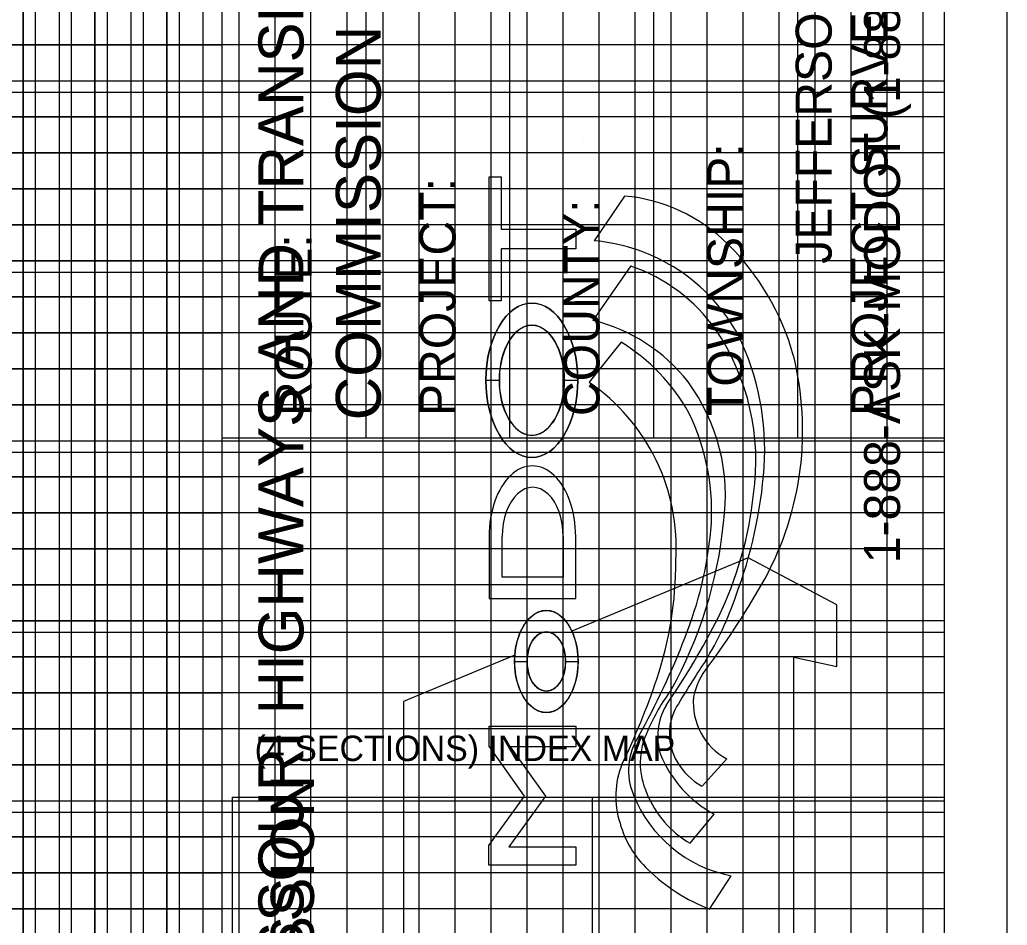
# Model space of a CAD drawing. Extents: x -0.2 to 31.7, y -0.2 to 20.6.
# Drawn here: x 28.681 to 31.425, y 5.654 to 8.169 of the extents above; entities that cross this region are included whole.
import ezdxf

# ---------------------------------------------------------------- set-up
doc = ezdxf.new("R2010")
doc.units = 0
for name, color, linetype in [('Border-Border', 7, 'Continuous'), ('Border-Bridge survey map and note', 7, 'Continuous'), ('Border-Cookie Cutter Template', 7, 'Continuous'), ('Border-English bridge partial major lines', 7, 'Continuous'), ('Border-English bridge partial minor lines', 7, 'Continuous'), ('Border-English bridge xsection major lines', 7, 'Continuous'), ('Border-English bridge xsection minor lines', 7, 'Continuous'), ('Border-English xsection major lines', 7, 'Continuous'), ('Border-English xsection minor lines', 7, 'Continuous'), ('Border-Full profile major grid lines', 7, 'Continuous'), ('Border-Geopak xsection major grid lines', 7, 'Continuous'), ('Border-Geopak xsection minor lines 1', 7, 'Continuous'), ('Border-Geopak xsection minor lines 2', 7, 'Continuous'), ('Border-Plan-profile major grid lines', 7, 'Continuous'), ('Border-Plotting block', 7, 'Continuous'), ('Border-Title block - A-size Landscape Electronic Seal', 7, 'Continuous'), ('Border-Title block - Final Plans Consultant Manual Seal', 7, 'Continuous'), ('Border-Title block - Final Plans Electronic Seal', 7, 'Continuous'), ('Border-Title block - Location Survey Electronic Seal', 7, 'Continuous'), ('Border-Xsection shape', 7, 'Continuous')]:
    doc.layers.add(name, color=color, linetype=linetype)

msp = doc.modelspace()

# ---------------------------------------------------------------- linework, layer by layer
at = {"layer": 'Border-Border'}
msp.add_line((31.25, 20.375), (31.25, 0), dxfattribs=at)
at = {"layer": 'Border-Bridge survey map and note'}
msp.add_line((30.2719, 6.0094), (30.2719, 3.9921), dxfattribs=at)
msp.add_lwpolyline([(29.2719, 3.9921), (29.2719, 6.0094), (31.2499, 6.0094)], dxfattribs=at)
at = {"layer": 'Border-Cookie Cutter Template'}
for p, q in [((29.2421, 20.375), (29.2421, 0)), ((31.2499, 20.375), (31.2499, 0))]:
    msp.add_line(p, q, dxfattribs=at)
at = {"layer": 'Border-English bridge partial major lines'}
for p, q in [((29.4899, 4), (29.4899, 20.375)), ((30.4899, 20.375), (30.4899, 4)), ((0, 8), (31.2499, 8)), ((0, 7), (31.2499, 7)), ((0, 6), (31.2499, 6))]:
    msp.add_line(p, q, dxfattribs=at)
at = {"layer": 'Border-English bridge partial minor lines'}
for p, q in [((28.6899, 20.375), (28.6899, 4)), ((28.7899, 20.375), (28.7899, 4)), ((28.8899, 20.375), (28.8899, 4)), ((28.9899, 20.375), (28.9899, 4)), ((29.0899, 20.375), (29.0899, 4)), ((29.1899, 20.375), (29.1899, 4)), ((29.2899, 20.375), (29.2899, 4)), ((29.3899, 20.375), (29.3899, 4)), ((29.5899, 20.375), (29.5899, 4)), ((29.6899, 20.375), (29.6899, 4)), ((29.7899, 20.375), (29.7899, 4)), ((29.8899, 20.375), (29.8899, 4)), ((29.9899, 20.375), (29.9899, 4)), ((30.0899, 20.375), (30.0899, 4)), ((30.1899, 20.375), (30.1899, 4)), ((30.2899, 20.375), (30.2899, 4)), ((30.3899, 20.375), (30.3899, 4)), ((30.5899, 20.375), (30.5899, 4)), ((30.6899, 20.375), (30.6899, 4)), ((30.7899, 20.375), (30.7899, 4)), ((30.8899, 20.375), (30.8899, 4)), ((30.9899, 20.375), (30.9899, 4)), ((31.0899, 20.375), (31.0899, 4)), ((31.1899, 20.375), (31.1899, 4)), ((31.2499, 8.1), (0, 8.1)), ((31.2499, 7.9), (0, 7.9)), ((31.2499, 7.8), (0, 7.8)), ((31.2499, 7.7), (0, 7.7)), ((31.2499, 7.6), (0, 7.6)), ((31.2499, 7.5), (0, 7.5)), ((31.2499, 7.4), (0, 7.4)), ((31.2499, 7.3), (0, 7.3)), ((31.2499, 7.2), (0, 7.2)), ((31.2499, 7.1), (0, 7.1)), ((31.2499, 6.9), (0, 6.9)), ((31.2499, 6.8), (0, 6.8)), ((31.2499, 6.7), (0, 6.7)), ((31.2499, 6.6), (0, 6.6)), ((31.2499, 6.5), (0, 6.5)), ((31.2499, 6.4), (0, 6.4)), ((31.2499, 6.3), (0, 6.3)), ((31.2499, 6.2), (0, 6.2)), ((31.2499, 6.1), (0, 6.1)), ((31.2499, 5.9), (0, 5.9)), ((31.2499, 5.8), (0, 5.8)), ((31.2499, 5.7), (0, 5.7))]:
    msp.add_line(p, q, dxfattribs=at)
at = {"layer": 'Border-English bridge xsection major lines'}
for p, q in [((29.4899, 3.9921), (29.4899, 20.375)), ((30.4899, 20.375), (30.4899, 3.9921)), ((0, 8), (31.2499, 8)), ((0, 7), (31.2499, 7)), ((0, 6), (31.2499, 6))]:
    msp.add_line(p, q, dxfattribs=at)
at = {"layer": 'Border-English bridge xsection minor lines'}
for p, q in [((28.6899, 20.375), (28.6899, 3.9921)), ((28.7899, 20.375), (28.7899, 3.9921)), ((28.8899, 20.375), (28.8899, 3.9921)), ((28.9899, 20.375), (28.9899, 3.9921)), ((29.0899, 20.375), (29.0899, 3.9921)), ((29.1899, 20.375), (29.1899, 3.9921)), ((29.2899, 20.375), (29.2899, 3.9921)), ((29.3899, 20.375), (29.3899, 3.9921)), ((29.5899, 20.375), (29.5899, 3.9921)), ((29.6899, 20.375), (29.6899, 3.9921)), ((29.7899, 20.375), (29.7899, 3.9921)), ((29.8899, 20.375), (29.8899, 3.9921)), ((29.9899, 20.375), (29.9899, 3.9921)), ((30.0899, 20.375), (30.0899, 3.9921)), ((30.1899, 20.375), (30.1899, 3.9921)), ((30.2899, 20.375), (30.2899, 3.9921)), ((30.3899, 20.375), (30.3899, 3.9921)), ((30.5899, 20.375), (30.5899, 3.9921)), ((30.6899, 20.375), (30.6899, 3.9921)), ((30.7899, 20.375), (30.7899, 3.9921)), ((30.8899, 20.375), (30.8899, 3.9921)), ((30.9899, 20.375), (30.9899, 3.9921)), ((31.0899, 20.375), (31.0899, 3.9921)), ((31.1899, 20.375), (31.1899, 3.9921)), ((31.2499, 8.1), (0, 8.1)), ((31.2499, 7.9), (0, 7.9)), ((31.2499, 7.8), (0, 7.8)), ((31.2499, 7.7), (0, 7.7)), ((31.2499, 7.6), (0, 7.6)), ((31.2499, 7.5), (0, 7.5)), ((31.2499, 7.4), (0, 7.4)), ((31.2499, 7.3), (0, 7.3)), ((31.2499, 7.2), (0, 7.2)), ((31.2499, 7.1), (0, 7.1)), ((31.2499, 6.9), (0, 6.9)), ((31.2499, 6.8), (0, 6.8)), ((31.2499, 6.7), (0, 6.7)), ((31.2499, 6.6), (0, 6.6)), ((31.2499, 6.5), (0, 6.5)), ((31.2499, 6.4), (0, 6.4)), ((31.2499, 6.3), (0, 6.3)), ((31.2499, 6.2), (0, 6.2)), ((31.2499, 6.1), (0, 6.1)), ((31.2499, 5.9), (0, 5.9)), ((31.2499, 5.8), (0, 5.8)), ((31.2499, 5.7), (0, 5.7))]:
    msp.add_line(p, q, dxfattribs=at)
at = {"layer": 'Border-English xsection major lines'}
for p, q in [((0, 8), (29.2421, 8)), ((0, 7), (29.2421, 7)), ((0, 6), (29.2421, 6))]:
    msp.add_line(p, q, dxfattribs=at)
at = {"layer": 'Border-English xsection minor lines'}
for p, q in [((28.6899, 0), (28.6899, 20.375)), ((28.8899, 0), (28.8899, 20.375)), ((29.0899, 0), (29.0899, 20.375)), ((0, 7.8), (29.2421, 7.8)), ((0, 7.6), (29.2421, 7.6)), ((0, 7.4), (29.2421, 7.4)), ((0, 7.2), (29.2421, 7.2)), ((0, 6.8), (29.2421, 6.8)), ((0, 6.6), (29.2421, 6.6)), ((0, 6.4), (29.2421, 6.4)), ((0, 6.2), (29.2421, 6.2)), ((0, 5.8), (29.2421, 5.8))]:
    msp.add_line(p, q, dxfattribs=at)
at = {"layer": 'Border-Full profile major grid lines'}
for p, q in [((29.2421, 7.5), (0, 7.5)), ((29.2421, 6.5), (0, 6.5))]:
    msp.add_line(p, q, dxfattribs=at)
at = {"layer": 'Border-Geopak xsection major grid lines'}
for p, q in [((0, 8), (29.2421, 8)), ((0, 7), (29.2421, 7)), ((0, 6), (29.2421, 6))]:
    msp.add_line(p, q, dxfattribs=at)
at = {"layer": 'Border-Geopak xsection minor lines 1'}
for p, q in [((28.7249, 0), (28.7249, 20.375)), ((28.9249, 0), (28.9249, 20.375)), ((29.1249, 0), (29.1249, 20.375)), ((0, 8.1), (29.2421, 8.1)), ((0, 7.9), (29.2421, 7.9)), ((0, 7.7), (29.2421, 7.7)), ((0, 7.5), (29.2421, 7.5)), ((0, 7.3), (29.2421, 7.3)), ((0, 7.1), (29.2421, 7.1)), ((0, 6.9), (29.2421, 6.9)), ((0, 6.7), (29.2421, 6.7)), ((0, 6.5), (29.2421, 6.5)), ((0, 6.3), (29.2421, 6.3)), ((0, 6.1), (29.2421, 6.1)), ((0, 5.9), (29.2421, 5.9)), ((0, 5.7), (29.2421, 5.7))]:
    msp.add_line(p, q, dxfattribs=at)
at = {"layer": 'Border-Geopak xsection minor lines 2'}
for p, q in [((28.8249, 0), (28.8249, 20.375)), ((29.0249, 0), (29.0249, 20.375)), ((0, 7.8), (29.2421, 7.8)), ((0, 7.6), (29.2421, 7.6)), ((0, 7.4), (29.2421, 7.4)), ((0, 7.2), (29.2421, 7.2)), ((0, 6.8), (29.2421, 6.8)), ((0, 6.6), (29.2421, 6.6)), ((0, 6.4), (29.2421, 6.4)), ((0, 6.2), (29.2421, 6.2)), ((0, 5.8), (29.2421, 5.8))]:
    msp.add_line(p, q, dxfattribs=at)
at = {"layer": 'Border-Plan-profile major grid lines'}
for p, q in [((29.2421, 7.5), (0, 7.5)), ((29.2421, 6.5), (0, 6.5))]:
    msp.add_line(p, q, dxfattribs=at)
at = {"layer": 'Border-Plotting block'}
msp.add_lwpolyline([(-0.175, -0.2125), (31.4249, -0.2125), (31.4249, 20.5875), (-0.175, 20.5875)], close=True, dxfattribs=at)
at = {"layer": 'Border-Title block - A-size Landscape Electronic Seal'}
for p, q in [((31.25, 7.9671), (25.6536, 7.9671)), ((29.1165, 7.7171), (29.1165, 7.7171)), ((31.2499, 7.4671), (25.6536, 7.4671)), ((29.1165, 7.2171), (29.1165, 7.2171)), ((31.25, 6.9671), (25.6536, 6.9671)), ((29.1165, 6.7171), (29.1165, 6.7171)), ((31.25, 6.4671), (25.6536, 6.4671)), ((29.1165, 6.2171), (29.1165, 6.2171)), ((31.25, 5.9671), (25.6536, 5.9671)), ((29.1165, 5.7171), (29.1165, 5.7171))]:
    msp.add_line(p, q, dxfattribs=at)
at = {"layer": 'Border-Title block - Final Plans Consultant Manual Seal'}
for p, q in [((29.2421, 20.375), (29.2421, 0)), ((30.3615, 7.6797), (30.2769, 7.5555)), ((30.3791, 7.4854), (30.2733, 7.3343)), ((30.3522, 7.2734), (30.2628, 7.1622)), ((29.985, 6.7339), (29.985, 6.5615)), ((30.0213, 6.6209), (30.0213, 6.7339)), ((30.1912, 6.7339), (30.1912, 6.6209)), ((30.2258, 6.5615), (30.2258, 6.7339)), ((30.7053, 6.6744), (30.2153, 6.4706)), ((30.9517, 6.5441), (30.7053, 6.6744)), ((30.1912, 6.6209), (30.0213, 6.6209)), ((29.985, 6.5615), (30.2258, 6.5615)), ((30.9517, 6.373), (30.9517, 6.5441)), ((30.0565, 6.4045), (29.747, 6.2758)), ((30.8321, 5.5668), (30.8321, 6.3984)), ((30.8321, 6.3984), (30.9517, 6.373)), ((29.747, 6.2758), (29.747, 5.3974)), ((30.5767, 6.04), (30.646, 6.116)), ((30.5438, 5.8818), (30.6107, 5.9623)), ((30.5979, 5.6989), (30.6579, 5.7914))]:
    msp.add_line(p, q, dxfattribs=at)
for points in [[(29.9849, 7.389), (29.9849, 7.7334), (30.0184, 7.7334), (30.0184, 7.588), (30.2258, 7.588), (30.2258, 7.5334), (30.0184, 7.5334), (30.0184, 7.389)], [(30.2258, 5.8212), (29.9842, 5.8212), (29.9842, 5.8757), (30.0838, 6.0126), (29.985, 6.1513), (29.985, 6.2068), (30.2258, 6.2068), (30.2258, 6.1494), (30.0435, 6.1494), (30.1414, 6.0126), (30.0397, 5.8719), (30.2258, 5.8719)]]:
    msp.add_lwpolyline(points, close=True, dxfattribs=at)
for centre, radius, start, end in [((30.3202, 7.216), 0.4656, 45.1693, 84.902), ((30.2326, 7.0506), 0.5069, 28.5725, 84.9889), ((30.1542, 7.0462), 0.7029, 15.8221, 45.3322), ((30.2197, 7.0262), 0.486, 35.4806, 70.8474), ((30.1611, 6.8707), 0.477, 37.8205, 76.3964), ((30.0712, 6.9433), 0.6553, 351.9272, 33.854), ((30.0697, 6.8139), 0.5393, 29.2666, 58.4191), ((30.0168, 6.9735), 0.7342, 356.2526, 25.8037), ((29.9956, 7.0284), 0.8608, 331.4589, 14.0852), ((29.9506, 6.7041), 0.5543, 55.7274, 55.7276), ((29.9506, 6.7041), 0.5543, 356.1033, 55.7272), ((30.1104, 6.8473), 0.5315, 351.8718, 36.464), ((29.9769, 6.803), 0.6267, 355.2048, 25.9837), ((29.4842, 7.0174), 1.2685, 339.2778, 355.8465), ((29.6781, 6.964), 1.048, 334.3097, 353.8237), ((29.4488, 6.8906), 1.1937, 330.8019, 354.3058), ((29.5189, 6.8555), 1.0875, 338.3366, 354.4662), ((29.4882, 6.6604), 1.0155, 341.469, 0.3416), ((28.8337, 7.6858), 2.1957, 323.2547, 330.8755), ((29.842, 6.8469), 0.8742, 328.3334, 341.428), ((28.754, 7.4559), 2.0944, 325.3377, 333.1413), ((28.5215, 7.2271), 2.1518, 330.8271, 338.9455), ((33.303, 4.5835), 3.2616, 146.4094, 149.0393), ((30.7373, 6.252), 0.1877, 140.188, 168.8506), ((28.4178, 7.0312), 2.1483, 334.3727, 341.1665), ((30.9575, 5.9676), 0.5778, 143.8762, 156.8714), ((30.7295, 6.2721), 0.177, 174.7527, 241.8661), ((30.6205, 6.1797), 0.167, 149.4043, 197.7638), ((30.6386, 6.1857), 0.1526, 150.2552, 210.6413), ((30.5453, 6.0841), 0.1729, 147.0199, 203.0239), ((30.6045, 6.1048), 0.1996, 153.2735, 205.15), ((30.7669, 6.2525), 0.3295, 202.0629, 241.7201), ((30.5743, 6.012), 0.2373, 157.7092, 198.1728), ((30.6772, 6.212), 0.1993, 211.4954, 239.6897), ((30.7282, 6.1528), 0.3681, 201.7288, 258.9961), ((30.6828, 6.1237), 0.279, 201.8104, 240.1114), ((30.6128, 6.0089), 0.2733, 195.0361, 226.9912), ((30.7761, 6.1649), 0.4989, 225.4988, 249.0787)]:
    msp.add_arc(centre, radius, start, end, dxfattribs=at)
for centre, major_axis, ratio in [((30.1038, 7.168), (0, 0.2144), 0.595517), ((30.1038, 7.1679), (0, -0.153), 0.589579), ((30.1441, 6.3867), (0, 0.1416), 0.623747), ((30.1441, 6.3867), (0, 0.0823), 0.65252)]:
    msp.add_ellipse(centre, major_axis=major_axis, ratio=ratio, dxfattribs=at)
for centre, major_axis, ratio in [((30.1053, 6.7338), (0, -0.1961), 0.614143), ((30.1062, 6.7338), (0, -0.1368), 0.62091)]:
    msp.add_ellipse(centre, major_axis=major_axis, ratio=ratio, start_param=1.570796, end_param=4.712389, dxfattribs=at)
at = {"layer": 'Border-Title block - Final Plans Electronic Seal'}
for p, q in [((29.2421, 20.375), (29.2421, 0)), ((30.3615, 7.6797), (30.2769, 7.5555)), ((30.3791, 7.4854), (30.2733, 7.3343)), ((30.3522, 7.2734), (30.2628, 7.1622)), ((29.9761, 7.1679), (30.0136, 7.1679)), ((29.9761, 7.1679), (30.0136, 7.1679)), ((30.194, 7.1679), (30.2315, 7.1679)), ((30.194, 7.1679), (30.2315, 7.1679)), ((29.985, 6.7339), (29.985, 6.5615)), ((30.0213, 6.6209), (30.0213, 6.7339)), ((30.1912, 6.7339), (30.1912, 6.6209)), ((30.2258, 6.5615), (30.2258, 6.7339)), ((30.7053, 6.6744), (30.2153, 6.4706)), ((30.9517, 6.5441), (30.7053, 6.6744)), ((30.1912, 6.6209), (30.0213, 6.6209)), ((29.985, 6.5615), (30.2258, 6.5615)), ((30.9517, 6.373), (30.9517, 6.5441)), ((30.0565, 6.4045), (29.747, 6.2758)), ((30.8321, 5.5668), (30.8321, 6.3984)), ((30.8321, 6.3984), (30.9517, 6.373)), ((30.0558, 6.3867), (30.091, 6.3867)), ((30.0558, 6.3867), (30.091, 6.3867)), ((30.091, 6.3867), (30.0904, 6.3867)), ((30.091, 6.3867), (30.0904, 6.3867)), ((30.1978, 6.3867), (30.2325, 6.3867)), ((30.1978, 6.3867), (30.2325, 6.3867)), ((29.747, 6.2758), (29.747, 5.3974)), ((30.5767, 6.04), (30.646, 6.116)), ((30.5438, 5.8818), (30.6107, 5.9623)), ((30.5979, 5.6989), (30.6579, 5.7914))]:
    msp.add_line(p, q, dxfattribs=at)
for points in [[(29.9849, 7.389), (29.9849, 7.7334), (30.0184, 7.7334), (30.0184, 7.588), (30.2258, 7.588), (30.2258, 7.5334), (30.0184, 7.5334), (30.0184, 7.389)], [(30.2258, 5.8212), (29.9842, 5.8212), (29.9842, 5.8757), (30.0838, 6.0126), (29.985, 6.1513), (29.985, 6.2068), (30.2258, 6.2068), (30.2258, 6.1494), (30.0435, 6.1494), (30.1414, 6.0126), (30.0397, 5.8719), (30.2258, 5.8719)]]:
    msp.add_lwpolyline(points, close=True, dxfattribs=at)
for centre, radius, start, end in [((30.3202, 7.216), 0.4656, 45.1693, 84.902), ((30.2326, 7.0506), 0.5069, 28.5725, 84.9889), ((30.1542, 7.0462), 0.7029, 15.8221, 45.3322), ((30.2197, 7.0262), 0.486, 35.4806, 70.8474), ((30.1611, 6.8707), 0.477, 37.8205, 76.3964), ((30.0712, 6.9433), 0.6553, 351.9272, 33.854), ((30.0697, 6.8139), 0.5393, 29.2666, 58.4191), ((30.0168, 6.9735), 0.7342, 356.2526, 25.8037), ((29.9956, 7.0284), 0.8608, 331.4589, 14.0852), ((29.9506, 6.7041), 0.5543, 55.7274, 55.7276), ((29.9506, 6.7041), 0.5543, 356.1033, 55.7272), ((30.1104, 6.8473), 0.5315, 351.8718, 36.464), ((29.9769, 6.803), 0.6267, 355.2048, 25.9837), ((29.4842, 7.0174), 1.2685, 339.2778, 355.8465), ((29.6781, 6.964), 1.048, 334.3097, 353.8237), ((29.4488, 6.8906), 1.1937, 330.8019, 354.3058), ((29.5189, 6.8555), 1.0875, 338.3366, 354.4662), ((29.4882, 6.6604), 1.0155, 341.469, 0.3416), ((28.8337, 7.6858), 2.1957, 323.2547, 330.8755), ((29.842, 6.8469), 0.8742, 328.3334, 341.428), ((28.754, 7.4559), 2.0944, 325.3377, 333.1413), ((28.5215, 7.2271), 2.1518, 330.8271, 338.9455), ((33.303, 4.5835), 3.2616, 146.4094, 149.0393), ((30.7373, 6.252), 0.1877, 140.188, 168.8506), ((28.4178, 7.0312), 2.1483, 334.3727, 341.1665), ((30.9575, 5.9676), 0.5778, 143.8762, 156.8714), ((30.7295, 6.2721), 0.177, 174.7527, 241.8661), ((30.6205, 6.1797), 0.167, 149.4043, 197.7638), ((30.6386, 6.1857), 0.1526, 150.2552, 210.6413), ((30.5453, 6.0841), 0.1729, 147.0199, 203.0239), ((30.6045, 6.1048), 0.1996, 153.2735, 205.15), ((30.7669, 6.2525), 0.3295, 202.0629, 241.7201), ((30.5743, 6.012), 0.2373, 157.7092, 198.1728), ((30.6772, 6.212), 0.1993, 211.4954, 239.6897), ((30.7282, 6.1528), 0.3681, 201.7288, 258.9961), ((30.6828, 6.1237), 0.279, 201.8104, 240.1114), ((30.6128, 6.0089), 0.2733, 195.0361, 226.9912), ((30.7761, 6.1649), 0.4989, 225.4988, 249.0787)]:
    msp.add_arc(centre, radius, start, end, dxfattribs=at)
for centre, major_axis, ratio, start_param, end_param in [((30.1038, 7.1678), (0, -0.2144), 0.595517, 1.571051, 4.712134), ((30.1038, 7.1679), (0, -0.153), 0.589579, 1.570796, 4.712389), ((30.1038, 7.168), (0, 0.2144), 0.595517, 1.571051, 4.712134), ((30.1038, 7.1679), (0, -0.153), 0.589579, 4.712389, 7.853982), ((30.1053, 6.7338), (0, -0.1961), 0.614143, 1.570796, 4.712389), ((30.1062, 6.7338), (0, -0.1368), 0.62091, 1.570796, 4.712389), ((30.1441, 6.3867), (0, -0.1416), 0.623747, 1.570796, 4.712389), ((30.1441, 6.3867), (0, -0.0823), 0.65252, 1.570796, 4.712389), ((30.1441, 6.3867), (0, 0.1416), 0.623747, 1.570796, 4.712389), ((30.1441, 6.3867), (0, 0.0823), 0.65252, 1.570796, 4.712389)]:
    msp.add_ellipse(centre, major_axis=major_axis, ratio=ratio, start_param=start_param, end_param=end_param, dxfattribs=at)
at = {"layer": 'Border-Title block - Location Survey Electronic Seal'}
for p, q in [((29.2421, 20.375), (29.2421, 0)), ((29.6421, 13.0077), (29.6421, 7.0077)), ((30.0421, 13.0077), (30.0421, 7.0077)), ((30.4421, 13.0077), (30.4421, 7.0077)), ((30.8421, 13.0077), (30.8421, 7.0077)), ((30.6421, 8.0523), (30.6421, 8.0523)), ((30.6421, 8.0523), (30.6421, 8.0523)), ((29.8421, 7.9025), (29.8421, 7.9025)), ((30.2479, 7.8321), (30.2479, 7.8321)), ((29.4421, 7.7286), (29.4421, 7.7286)), ((29.2421, 7.0077), (31.25, 7.0077))]:
    msp.add_line(p, q, dxfattribs=at)
at = {"layer": 'Border-Xsection shape'}
msp.add_lwpolyline([(29.2421, 0), (0, 0), (0, 20.375), (29.2421, 20.375)], close=True, dxfattribs=at)

# ---------------------------------------------------------------- texts
at = {"layer": 'Border-Bridge survey map and note'}
msp.add_text('(4 SECTIONS) INDEX MAP', height=0.070563, dxfattribs=at).set_placement((29.3334, 6.1102))
at = {"layer": 'Border-Title block - Final Plans Consultant Manual Seal'}
for s, height, p in [('JEFFERSON CITY, MO 65102', 0.1, (30.937, 7.4914)), ('MISSOURI HIGHWAYS AND TRANSPORTATION', 0.125, (29.4692, 5.3667)), ('1-888-ASK-MODOT (1-888-275-6636)', 0.1, (31.127, 6.6597)), ('COMMISSION', 0.125, (29.6842, 7.0567))]:
    msp.add_text(s, height=height, rotation=90, dxfattribs=at).set_placement(p)
at = {"layer": 'Border-Title block - Final Plans Electronic Seal'}
for s, height, p in [('JEFFERSON CITY, MO 65102', 0.1, (30.937, 7.4914)), ('MISSOURI HIGHWAYS AND TRANSPORTATION', 0.125, (29.4692, 5.3667)), ('1-888-ASK-MODOT (1-888-275-6636)', 0.1, (31.127, 6.6597)), ('COMMISSION', 0.125, (29.6842, 7.0567))]:
    msp.add_text(s, height=height, rotation=90, dxfattribs=at).set_placement(p)
at = {"layer": 'Border-Title block - Location Survey Electronic Seal'}
for s, height, p in [('PROJECT SURVEYOR:', 0.1, (31.0921, 7.0685)), ('TOWNSHIP:', 0.1, (30.6921, 7.0685)), ('PROJECT:', 0.1, (29.8921, 7.0685)), ('COUNTY:', 0.1, (30.2921, 7.0685)), ('ROUTE:', 0.1, (29.4921, 7.0685)), ('SURVEY FOR: MISSOURI HIGHWAYS AND TRANSPORTATION COMMISSION', 0.12, (29.4984, 0.2231))]:
    msp.add_text(s, height=height, rotation=90, dxfattribs=at).set_placement(p)

doc.saveas('drawing.dxf')
